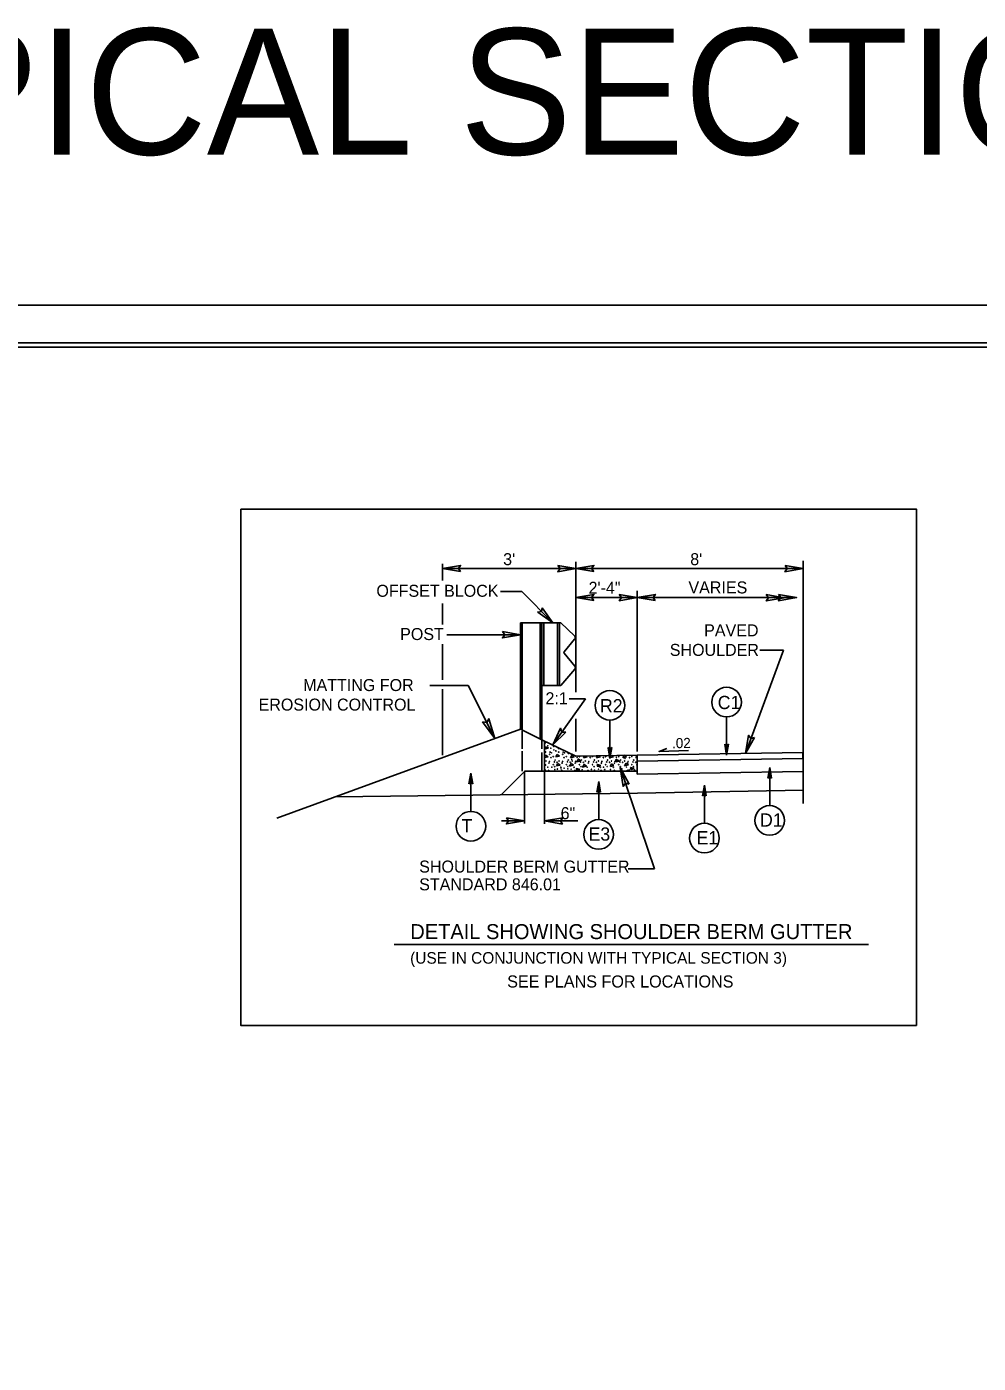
# Model space of a CAD drawing. Extents: x 981824 to 982276, y 44828 to 45204.
# Drawn here: x 982141 to 982186.4, y 45127.5 to 45191.2 of the extents above; entities that cross this region are included whole.
import ezdxf

# ---------------------------------------------------------------- set-up
doc = ezdxf.new("R2010")
doc.units = 0
for name, color, linetype in [('Default', 7, 'Continuous'), ('Old_Level_1', 7, 'Continuous'), ('Old_Level_11', 7, 'Continuous'), ('Old_Level_18', 7, 'Continuous'), ('Old_Level_2', 7, 'Continuous'), ('Old_Level_20', 7, 'Continuous'), ('Old_Level_3', 7, 'Continuous'), ('Old_Level_50', 7, 'Continuous'), ('Old_Level_51', 7, 'Continuous'), ('Typical Terminator CELL', 7, 'Continuous')]:
    doc.layers.add(name, color=color, linetype=linetype)

msp = doc.modelspace()

# ---------------------------------------------------------------- linework, layer by layer
at = {"layer": 'Default'}
msp.add_lwpolyline([(982172.566, 45156.753), (982171.165, 45156.704), (982171.532, 45156.842)], dxfattribs=at)
at = {"layer": 'Old_Level_1'}
for p, q in [((982160.849, 45164.848), (982160.849, 45165.637)), ((982160.849, 45165.418), (982167.199, 45165.418)), ((982167.199, 45159.531), (982167.199, 45165.739)), ((982167.199, 45165.418), (982178.031, 45165.418)), ((982163.603, 45164.324), (982164.62, 45164.324)), ((982164.62, 45164.324), (982166.102, 45162.838)), ((982167.199, 45164.036), (982170.128, 45164.036)), ((982170.128, 45156.7), (982170.128, 45164.361)), ((982170.128, 45164.036), (982177.72, 45164.036)), ((982160.849, 45162.752), (982160.849, 45163.748)), ((982164.565, 45162.838), (982166.485, 45162.838)), ((982164.565, 45157.76), (982164.565, 45162.838)), ((982164.648, 45157.716), (982164.648, 45162.838)), ((982165.5, 45157.302), (982165.5, 45162.838)), ((982165.586, 45157.262), (982165.586, 45162.838)), ((982165.673, 45159.84), (982165.673, 45162.838)), ((982166.333, 45159.84), (982166.333, 45162.838)), ((982166.419, 45159.84), (982166.419, 45162.838)), ((982167.139, 45162.204), (982166.485, 45162.838)), ((982161.054, 45162.267), (982164.565, 45162.267)), ((982167.141, 45162.053), (982166.641, 45161.444)), ((982160.849, 45160.122), (982160.849, 45161.807)), ((982166.639, 45161.385), (982167.156, 45160.761)), ((982177.098, 45161.528), (982175.281, 45156.61)), ((982175.963, 45161.528), (982177.098, 45161.528)), ((982167.153, 45160.623), (982166.485, 45159.84)), ((982160.235, 45159.845), (982162.076, 45159.845)), ((982160.849, 45156.533), (982160.849, 45159.663)), ((982162.076, 45159.845), (982163.338, 45157.312)), ((982165.586, 45159.84), (982166.485, 45159.84)), ((982167.66, 45159.216), (982166.102, 45157.013)), ((982166.883, 45159.216), (982167.66, 45159.216)), ((982167.199, 45156.7), (982167.199, 45158.264)), ((982164.565, 45157.76), (982152.954, 45153.517)), ((982164.565, 45157.76), (982165.586, 45157.259)), ((982164.565, 45157.75), (982164.565, 45157.76)), ((982164.639, 45156.826), (982164.639, 45157.662)), ((982165.586, 45157.262), (982167.199, 45156.478)), ((982165.586, 45156.826), (982165.586, 45157.262)), ((982165.713, 45155.764), (982165.713, 45157.202)), ((982174.388, 45156.523), (982174.299, 45157.043)), ((982174.388, 45156.972), (982174.299, 45157.043)), ((982174.388, 45156.523), (982174.31, 45157.033)), ((982174.322, 45157.022), (982174.388, 45156.523)), ((982174.388, 45156.523), (982174.337, 45157.011)), ((982174.351, 45157.004), (982174.388, 45156.523)), ((982174.388, 45156.523), (982174.362, 45156.993)), ((982174.376, 45156.984), (982174.388, 45156.523)), ((982174.388, 45156.523), (982174.481, 45157.043)), ((982174.481, 45157.043), (982174.388, 45156.972)), ((982174.463, 45157.033), (982174.388, 45156.523)), ((982174.388, 45156.523), (982174.454, 45157.022)), ((982174.44, 45157.011), (982174.388, 45156.523)), ((982174.388, 45156.523), (982174.425, 45157.004)), ((982174.411, 45156.993), (982174.388, 45156.523)), ((982174.388, 45156.523), (982174.403, 45156.984)), ((982174.388, 45156.972), (982174.388, 45156.523)), ((982164.639, 45155.764), (982164.639, 45156.723)), ((982165.586, 45155.772), (982165.586, 45156.658)), ((982165.713, 45156.447), (982165.759, 45156.528)), ((982165.874, 45156.448), (982165.713, 45156.411)), ((982165.759, 45156.528), (982165.874, 45156.448)), ((982166.246, 45156.44), (982166.313, 45156.564)), ((982166.425, 45156.482), (982166.246, 45156.44)), ((982166.313, 45156.564), (982166.425, 45156.482)), ((982166.36, 45156.886), (982166.372, 45156.827)), ((982166.372, 45156.827), (982166.436, 45156.848)), ((982166.94, 45156.404), (982167.006, 45156.528)), ((982167.12, 45156.448), (982166.94, 45156.404)), ((982167.006, 45156.528), (982167.12, 45156.448)), ((982167.199, 45156.478), (982170.128, 45156.527)), ((982167.563, 45156.404), (982167.608, 45156.482)), ((982167.744, 45156.448), (982167.563, 45156.404)), ((982167.695, 45156.484), (982167.744, 45156.448)), ((982168.19, 45156.404), (982168.239, 45156.492)), ((982168.369, 45156.448), (982168.19, 45156.404)), ((982168.302, 45156.495), (982168.369, 45156.448)), ((982168.826, 45156.37), (982168.736, 45156.886)), ((982168.826, 45156.82), (982168.736, 45156.886)), ((982168.826, 45156.37), (982168.746, 45156.879)), ((982168.758, 45156.87), (982168.826, 45156.37)), ((982168.826, 45156.37), (982168.772, 45156.858)), ((982168.788, 45156.848), (982168.826, 45156.37)), ((982168.826, 45156.37), (982168.799, 45156.842)), ((982168.812, 45156.404), (982168.868, 45156.506)), ((982168.993, 45156.448), (982168.812, 45156.404)), ((982168.815, 45156.831), (982168.826, 45156.37)), ((982168.826, 45156.37), (982168.921, 45156.886)), ((982168.921, 45156.886), (982168.826, 45156.82)), ((982168.904, 45156.879), (982168.826, 45156.37)), ((982168.826, 45156.37), (982168.892, 45156.87)), ((982168.878, 45156.858), (982168.826, 45156.37)), ((982168.826, 45156.37), (982168.867, 45156.848)), ((982168.855, 45156.842), (982168.826, 45156.37)), ((982168.826, 45156.37), (982168.838, 45156.831)), ((982168.826, 45156.82), (982168.826, 45156.37)), ((982168.916, 45156.506), (982168.993, 45156.448)), ((982169.437, 45156.404), (982169.501, 45156.518)), ((982169.618, 45156.448), (982169.437, 45156.404)), ((982169.526, 45156.518), (982169.618, 45156.448)), ((982170.059, 45156.404), (982170.128, 45156.521)), ((982170.128, 45156.418), (982170.059, 45156.404)), ((982170.128, 45156.527), (982178.018, 45156.657)), ((982170.128, 45155.764), (982170.128, 45156.527)), ((982170.128, 45156.135), (982170.128, 45156.524)), ((982170.128, 45156.236), (982178.023, 45156.366)), ((982178.031, 45156.264), (982178.031, 45154.215)), ((982162.2, 45155.669), (982162.108, 45155.152)), ((982162.2, 45155.669), (982162.122, 45155.16)), ((982162.136, 45155.172), (982162.2, 45155.669)), ((982162.2, 45155.669), (982162.149, 45155.18)), ((982162.161, 45155.189), (982162.2, 45155.669)), ((982162.2, 45155.669), (982162.172, 45155.203)), ((982162.186, 45155.209), (982162.2, 45155.669)), ((982162.2, 45155.669), (982162.29, 45155.152)), ((982162.278, 45155.16), (982162.2, 45155.669)), ((982162.2, 45155.669), (982162.263, 45155.172)), ((982162.252, 45155.18), (982162.2, 45155.669)), ((982162.2, 45155.669), (982162.241, 45155.189)), ((982162.227, 45155.203), (982162.2, 45155.669)), ((982162.2, 45155.669), (982162.215, 45155.209)), ((982162.2, 45155.219), (982162.2, 45155.669)), ((982164.75, 45155.748), (982163.644, 45154.639)), ((982165.713, 45155.764), (982164.75, 45155.764)), ((982164.75, 45153.262), (982164.75, 45155.748)), ((982170.128, 45155.764), (982165.713, 45155.764)), ((982165.713, 45153.254), (982165.713, 45155.764)), ((982166.281, 45156.01), (982166.347, 45156.132)), ((982166.459, 45156.052), (982166.281, 45156.01)), ((982166.347, 45156.132), (982166.459, 45156.052)), ((982166.903, 45155.998), (982166.972, 45156.123)), ((982167.084, 45156.044), (982166.903, 45155.998)), ((982166.972, 45156.123), (982167.084, 45156.044)), ((982168.83, 45155.986), (982168.896, 45156.111)), ((982169.007, 45156.03), (982168.83, 45155.986)), ((982168.896, 45156.111), (982169.007, 45156.03)), ((982170.956, 45151.106), (982169.314, 45155.945)), ((982169.526, 45156.014), (982169.595, 45156.138)), ((982169.705, 45156.058), (982169.526, 45156.014)), ((982169.595, 45156.138), (982169.705, 45156.058)), ((982170.128, 45155.764), (982170.128, 45155.614)), ((982170.128, 45155.614), (982178.033, 45155.744)), ((982176.439, 45155.945), (982176.347, 45155.425)), ((982176.439, 45155.945), (982176.358, 45155.437)), ((982176.371, 45155.448), (982176.439, 45155.945)), ((982176.439, 45155.945), (982176.385, 45155.454)), ((982176.395, 45155.466), (982176.439, 45155.945)), ((982176.439, 45155.945), (982176.41, 45155.473)), ((982176.424, 45155.483), (982176.439, 45155.945)), ((982176.439, 45155.945), (982176.529, 45155.425)), ((982176.514, 45155.437), (982176.439, 45155.945)), ((982176.439, 45155.945), (982176.502, 45155.448)), ((982176.491, 45155.454), (982176.439, 45155.945)), ((982176.439, 45155.945), (982176.477, 45155.466)), ((982176.463, 45155.473), (982176.439, 45155.945)), ((982176.439, 45155.945), (982176.451, 45155.483)), ((982176.439, 45155.495), (982176.439, 45155.945)), ((982162.2, 45155.219), (982162.108, 45155.152)), ((982162.29, 45155.152), (982162.2, 45155.219)), ((982168.29, 45155.277), (982168.198, 45154.758)), ((982168.29, 45155.277), (982168.21, 45154.768)), ((982168.223, 45154.78), (982168.29, 45155.277)), ((982168.29, 45155.277), (982168.235, 45154.786)), ((982168.247, 45154.797), (982168.29, 45155.277)), ((982168.29, 45155.277), (982168.262, 45154.804)), ((982168.276, 45154.815), (982168.29, 45155.277)), ((982168.29, 45155.277), (982168.379, 45154.758)), ((982168.365, 45154.768), (982168.29, 45155.277)), ((982168.29, 45155.277), (982168.354, 45154.78)), ((982168.342, 45154.786), (982168.29, 45155.277)), ((982168.29, 45155.277), (982168.328, 45154.797)), ((982168.313, 45154.804), (982168.29, 45155.277)), ((982168.29, 45155.277), (982168.302, 45154.815)), ((982168.29, 45154.826), (982168.29, 45155.277)), ((982173.331, 45155.102), (982173.239, 45154.583)), ((982173.331, 45155.102), (982173.251, 45154.593)), ((982173.264, 45154.605), (982173.331, 45155.102)), ((982173.331, 45155.102), (982173.276, 45154.611)), ((982173.288, 45154.622), (982173.331, 45155.102)), ((982173.331, 45155.102), (982173.303, 45154.629)), ((982173.317, 45154.64), (982173.331, 45155.102)), ((982173.331, 45155.102), (982173.42, 45154.583)), ((982173.406, 45154.593), (982173.331, 45155.102)), ((982173.331, 45155.102), (982173.395, 45154.605)), ((982173.383, 45154.611), (982173.331, 45155.102)), ((982173.331, 45155.102), (982173.369, 45154.622)), ((982173.354, 45154.629), (982173.331, 45155.102)), ((982173.331, 45155.102), (982173.343, 45154.64)), ((982173.331, 45154.651), (982173.331, 45155.102)), ((982176.439, 45155.495), (982176.347, 45155.425)), ((982176.529, 45155.425), (982176.439, 45155.495)), ((982155.749, 45154.539), (982170.138, 45154.722)), ((982168.29, 45154.826), (982168.198, 45154.758)), ((982168.379, 45154.758), (982168.29, 45154.826)), ((982170.14, 45154.722), (982178.047, 45154.852)), ((982173.331, 45154.651), (982173.239, 45154.583)), ((982173.42, 45154.583), (982173.331, 45154.651)), ((982163.66, 45153.398), (982164.75, 45153.398)), ((982165.713, 45153.39), (982167.292, 45153.39)), ((982170.956, 45151.106), (982169.692, 45151.106))]:
    msp.add_line(p, q, dxfattribs=at)
msp.add_lwpolyline([(982178.031, 45165.782), (982178.031, 45156.188)], dxfattribs=at)
for points in [[(982165.895, 45156.88), (982165.727, 45156.928), (982165.748, 45156.827)], [(982167.432, 45156.261), (982167.321, 45156.339), (982167.255, 45156.213)], [(982169.275, 45156.263), (982169.107, 45156.311), (982169.128, 45156.21)], [(982178.018, 45156.657), (982170.128, 45156.527), (982170.128, 45156.236), (982178.023, 45156.366)], [(982167.397, 45155.84), (982167.229, 45155.888), (982167.25, 45155.787)], [(982167.703, 45156.009), (982167.592, 45156.087), (982167.526, 45155.961)], [(982168.39, 45156.04), (982168.222, 45156.088), (982168.243, 45155.987)], [(982169.978, 45155.897), (982169.81, 45155.945), (982169.831, 45155.844)]]:
    msp.add_lwpolyline(points, close=True, dxfattribs=at)
for centre in [(982165.764, 45157.119), (982165.866, 45156.973), (982166.147, 45156.942), (982165.759, 45156.673), (982165.778, 45156.247), (982165.953, 45156.567), (982165.972, 45156.673), (982166.01, 45156.854), (982166.016, 45156.41), (982166.034, 45156.636), (982166.122, 45156.46), (982166.153, 45156.773), (982166.215, 45156.291), (982166.252, 45156.729), (982166.384, 45156.673), (982166.402, 45156.247), (982166.578, 45156.567), (982166.597, 45156.673), (982166.641, 45156.41), (982166.658, 45156.636), (982166.746, 45156.46), (982166.839, 45156.291), (982166.849, 45156.611), (982167.009, 45156.325), (982167.027, 45156.247), (982167.265, 45156.41), (982167.371, 45156.46), (982167.464, 45156.291), (982167.651, 45156.247), (982167.889, 45156.41), (982167.995, 45156.46), (982168.088, 45156.291), (982168.276, 45156.247), (982168.514, 45156.41), (982168.619, 45156.46), (982168.712, 45156.291), (982168.9, 45156.247), (982169.138, 45156.41), (982169.244, 45156.46), (982169.337, 45156.291), (982169.525, 45156.247), (982169.545, 45156.365), (982169.763, 45156.41), (982169.868, 45156.46), (982169.961, 45156.291), (982165.753, 45155.805), (982165.764, 45156.051), (982165.866, 45155.948), (982165.907, 45155.8), (982165.922, 45156.148), (982165.947, 45156.228), (982166.06, 45155.954), (982166.122, 45156.073), (982166.178, 45156.203), (982166.196, 45155.979), (982166.2, 45155.841), (982166.309, 45156.186), (982166.323, 45155.863), (982166.49, 45155.948), (982166.495, 45155.873), (982166.532, 45155.8), (982166.547, 45156.148), (982166.572, 45156.228), (982166.644, 45155.902), (982166.746, 45156.073), (982166.802, 45156.203), (982166.817, 45155.873), (982166.82, 45155.979), (982166.933, 45156.186), (982166.978, 45155.852), (982167.115, 45155.948), (982167.156, 45155.8), (982167.171, 45156.148), (982167.196, 45156.228), (982167.371, 45156.073), (982167.427, 45156.203), (982167.445, 45155.979), (982167.504, 45155.83), (982167.558, 45156.186), (982167.739, 45155.948), (982167.781, 45155.8), (982167.796, 45156.148), (982167.821, 45156.228), (982167.944, 45155.852), (982167.995, 45156.073), (982168.051, 45156.203), (982168.069, 45155.979), (982168.094, 45155.811), (982168.182, 45156.186), (982168.288, 45155.857), (982168.364, 45155.948), (982168.405, 45155.8), (982168.42, 45156.148), (982168.445, 45156.228), (982168.522, 45155.954), (982168.58, 45155.839), (982168.619, 45156.073), (982168.676, 45156.203), (982168.694, 45155.979), (982168.807, 45156.186), (982168.851, 45155.841), (982168.988, 45155.948), (982169.03, 45155.8), (982169.045, 45156.148), (982169.07, 45156.228), (982169.244, 45156.073), (982169.3, 45156.203), (982169.318, 45155.979), (982169.399, 45155.863), (982169.431, 45156.186), (982169.654, 45155.8), (982169.669, 45156.148), (982169.694, 45156.228), (982169.737, 45155.825), (982169.868, 45156.073), (982169.925, 45156.203), (982169.943, 45155.979), (982170.005, 45155.82), (982170.056, 45156.186), (982170.11, 45156.062)]:
    msp.add_circle(centre, 0.0088, dxfattribs=at)
for centre, radius, start, end in [((982167.06, 45162.126), 0.111, 318.61464, 44.30598), ((982166.682, 45161.413), 0.0515, 143.23993, 213.38993), ((982167.065, 45160.695), 0.113, 320.13423, 35.76152), ((982169.613, 45155.948), 0.0088, 353.86175, 188.01785)]:
    msp.add_arc(centre, radius, start, end, dxfattribs=at)
at = {"layer": 'Old_Level_11'}
msp.add_lwpolyline([(982151.233, 45168.255), (982183.435, 45168.255), (982183.435, 45143.644), (982151.233, 45143.644)], close=True, dxfattribs=at)
at = {"layer": 'Old_Level_18'}
msp.add_lwpolyline([(982227.72, 45175.969), (982107.72, 45175.969), (982107.72, 45091.969), (982227.72, 45091.969)], close=True, dxfattribs=at)
at = {"layer": 'Old_Level_2'}
for p, q in [((982168.826, 45158.196), (982168.826, 45156.37)), ((982174.388, 45158.351), (982174.388, 45156.523)), ((982162.2, 45153.848), (982162.2, 45155.669)), ((982176.439, 45154.118), (982176.439, 45155.945)), ((982168.29, 45153.45), (982168.29, 45155.277)), ((982173.331, 45153.275), (982173.331, 45155.102))]:
    msp.add_line(p, q, dxfattribs=at)
for centre in [(982168.826, 45158.9), (982174.388, 45159.054), (982162.2, 45153.139), (982176.438, 45153.416), (982168.287, 45152.747), (982173.328, 45152.572)]:
    msp.add_circle(centre, 0.706, dxfattribs=at)
at = {"layer": 'Old_Level_3'}
msp.add_line((982181.154, 45147.497), (982158.546, 45147.497), dxfattribs=at)
at = {"layer": 'Old_Level_50'}
msp.add_lwpolyline([(982228.72, 45176.173), (982095.4, 45176.173), (982095.4, 45091.765), (982228.72, 45091.765)], close=True, dxfattribs=at)
at = {"layer": 'Old_Level_51'}
msp.add_lwpolyline([(982229.08, 45177.969), (982094.36, 45177.969), (982094.36, 45089.969), (982229.08, 45089.969)], close=True, dxfattribs=at)
at = {"layer": 'Typical Terminator CELL'}
for points in [[(982161.707, 45165.27), (982160.849, 45165.418), (982161.711, 45165.571), (982161.602, 45165.418)], [(982166.342, 45165.566), (982167.199, 45165.418), (982166.337, 45165.266), (982166.447, 45165.418)], [(982168.057, 45165.27), (982167.199, 45165.418), (982168.061, 45165.571), (982167.952, 45165.418)], [(982177.174, 45165.566), (982178.031, 45165.418), (982177.169, 45165.266), (982177.279, 45165.418)], [(982168.057, 45163.888), (982167.199, 45164.036), (982168.061, 45164.189), (982167.952, 45164.036)], [(982169.271, 45164.184), (982170.128, 45164.036), (982169.266, 45163.884), (982169.376, 45164.036)], [(982170.986, 45163.888), (982170.128, 45164.036), (982170.99, 45164.189), (982170.881, 45164.036)], [(982176.278, 45164.178), (982177.136, 45164.03), (982176.274, 45163.878), (982176.383, 45164.03)], [(982176.863, 45164.184), (982177.72, 45164.036), (982176.858, 45163.884), (982176.968, 45164.036)], [(982165.6, 45163.549), (982166.102, 45162.838), (982165.385, 45163.34), (982165.57, 45163.37)], [(982163.708, 45162.415), (982164.565, 45162.267), (982163.703, 45162.115), (982163.813, 45162.267)], [(982162.755, 45158.108), (982163.338, 45157.312), (982163.057, 45158.264), (982162.958, 45158.076)], [(982166.717, 45157.629), (982166.102, 45157.013), (982166.474, 45157.806), (982166.536, 45157.628)], [(982175.717, 45157.363), (982175.281, 45156.61), (982175.437, 45157.472), (982175.542, 45157.316)], [(982169.75, 45155.143), (982169.314, 45155.945), (982169.453, 45155.037), (982169.568, 45155.197)], [(982163.893, 45153.546), (982164.75, 45153.398), (982163.888, 45153.246), (982163.998, 45153.398)], [(982166.571, 45153.242), (982165.713, 45153.39), (982166.575, 45153.542), (982166.466, 45153.39)]]:
    msp.add_lwpolyline(points, close=True, dxfattribs=at)

# ---------------------------------------------------------------- texts
at = {"layer": 'Old_Level_1'}
for s, height, p in [('TYPICAL SECTIONS', 6, (982125.989, 45185.148)), ("3'", 0.5717, (982163.737, 45165.579)), ("8'", 0.5717, (982172.654, 45165.579)), ('OFFSET BLOCK', 0.57168, (982157.695, 45164.072)), ('2\'-4"', 0.5717, (982167.808, 45164.216)), ('VARIES', 0.5717, (982172.568, 45164.233)), ('PAVED', 0.5717, (982173.316, 45162.188)), ('POST', 0.5717, (982158.828, 45162.011)), ('SHOULDER', 0.5717, (982171.678, 45161.256)), ('MATTING FOR', 0.57168, (982154.206, 45159.581)), ('2:1', 0.5716, (982165.753, 45158.952)), ('EROSION CONTROL', 0.57168, (982152.08, 45158.649)), ('6"', 0.5717, (982166.475, 45153.475)), ('SHOULDER BERM GUTTER', 0.57168, (982159.735, 45150.931)), ('STANDARD 846.01', 0.57168, (982159.735, 45150.084)), ('DETAIL SHOWING SHOULDER BERM GUTTER', 0.71446, (982159.31, 45147.76)), ('SEE PLANS FOR LOCATIONS', 0.576, (982163.928, 45145.454))]:
    msp.add_text(s, height=height, dxfattribs=at).set_placement(p)
at = {"layer": 'Old_Level_2'}
msp.add_text('.02  ', height=0.48, rotation=1.14402, dxfattribs=at).set_placement((982171.79, 45156.854))
at = {"layer": 'Old_Level_20'}
for s, p in [('R2', (982168.35, 45158.565)), ('C1', (982173.962, 45158.72)), ('D1', (982175.979, 45153.12)), ('T ', (982161.751, 45152.845)), ('E3', (982167.805, 45152.452)), ('E1', (982172.952, 45152.277))]:
    msp.add_text(s, height=0.6316, dxfattribs=at).set_placement(p)
at = {"layer": 'Old_Level_3'}
msp.add_text('(USE IN CONJUNCTION WITH TYPICAL SECTION 3)', height=0.55074, dxfattribs=at).set_placement((982159.303, 45146.589))

doc.saveas('drawing.dxf')
